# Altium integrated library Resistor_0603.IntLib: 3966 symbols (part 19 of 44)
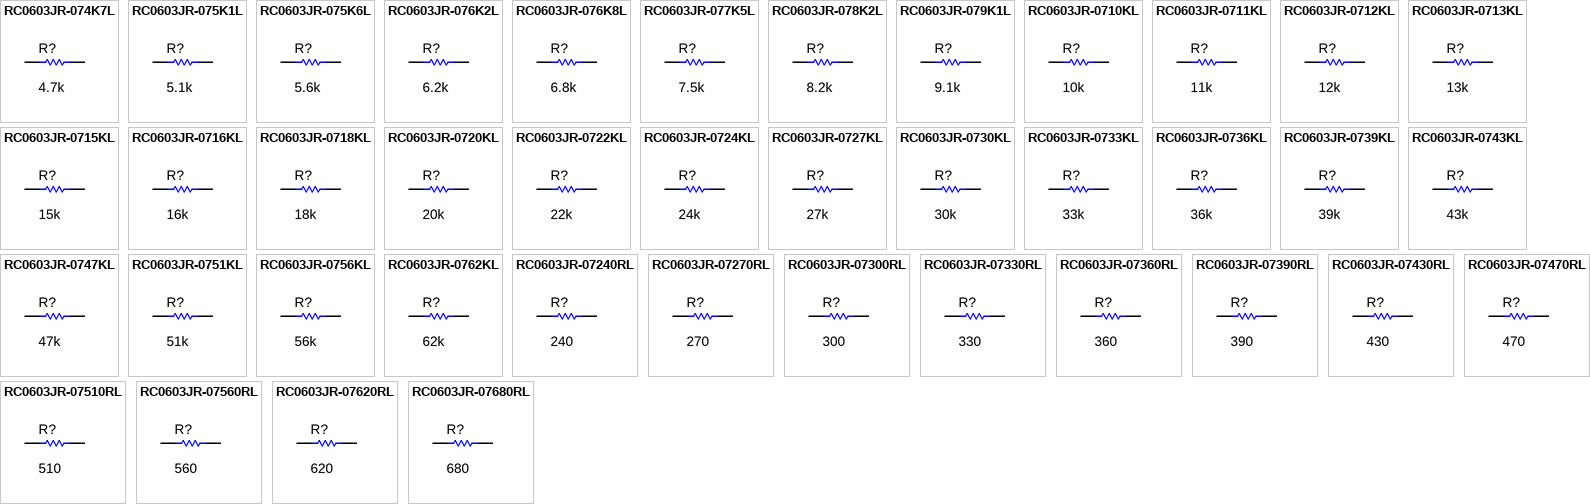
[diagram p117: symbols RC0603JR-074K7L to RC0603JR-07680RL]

## RC0603JR-0736KL
designator R?  ValueDisplayed: 36k  (hidden comment: RC0603JR-0736KL)
RES, 36 k, 5%, 0.1 W, 0603; Manufacturer: Yageo America; CompType: Resistor; Value: 36k; Res_ohm: 36000; Value_Code: 36k0; Tolerance_%: 5; Power_W: 0.1; Value2: 0.1W; VDC_V: 50; TempCo: 100 ppm/C; SizeArea_mm2: 1.28; SizeX_mm: 1.6; SizeY_mm: 0.8; SizeZ_mm: 1; EIA_Code: E24; U/M: EA; AEC Category: Q200
signal-integrity model Resistor
simulation model Resistor
footprint 0603
footprint 0603M
footprint 0603L
footprint 0603_HV
footprint 0603S
pins: 1, 2

## RC0603JR-0739KL
designator R?  ValueDisplayed: 39k  (hidden comment: RC0603JR-0739KL)
RES, 39 k, 5%, 0.1 W, 0603; Manufacturer: Yageo America; CompType: Resistor; Value: 39k; Res_ohm: 39000; Value_Code: 39k0; Tolerance_%: 5; Power_W: 0.1; Value2: 0.1W; VDC_V: 50; TempCo: 100 ppm/C; SizeArea_mm2: 1.28; SizeX_mm: 1.6; SizeY_mm: 0.8; SizeZ_mm: 1; EIA_Code: E24; U/M: EA; AEC Category: Q200
signal-integrity model Resistor
simulation model Resistor
footprint 0603
footprint 0603M
footprint 0603L
footprint 0603_HV
footprint 0603S
pins: 1, 2

## RC0603JR-0743KL
designator R?  ValueDisplayed: 43k  (hidden comment: RC0603JR-0743KL)
RES, 43 k, 5%, 0.1 W, 0603; Manufacturer: Yageo America; CompType: Resistor; Value: 43k; Res_ohm: 43000; Value_Code: 43k0; Tolerance_%: 5; Power_W: 0.1; Value2: 0.1W; VDC_V: 50; TempCo: 100 ppm/C; SizeArea_mm2: 1.28; SizeX_mm: 1.6; SizeY_mm: 0.8; SizeZ_mm: 1; EIA_Code: E24; U/M: EA; AEC Category: Q200
signal-integrity model Resistor
simulation model Resistor
footprint 0603
footprint 0603M
footprint 0603L
footprint 0603_HV
footprint 0603S
pins: 1, 2

## RC0603JR-0747KL
designator R?  ValueDisplayed: 47k  (hidden comment: RC0603JR-0747KL)
RES, 47 k, 5%, 0.1 W, 0603; Manufacturer: Yageo America; CompType: Resistor; Value: 47k; Res_ohm: 47000; Value_Code: 47k0; Tolerance_%: 5; Power_W: 0.1; Value2: 0.1W; VDC_V: 50; TempCo: 100 ppm/C; SizeArea_mm2: 1.28; SizeX_mm: 1.6; SizeY_mm: 0.8; SizeZ_mm: 1; EIA_Code: E24; U/M: EA; AEC Category: Q200; Green_Lifecycle: Active; Green_REACh: Passed
signal-integrity model Resistor
simulation model Resistor
footprint 0603
footprint 0603M
footprint 0603L
footprint 0603_HV
footprint 0603S
pins: 1, 2

## RC0603JR-0751KL
designator R?  ValueDisplayed: 51k  (hidden comment: RC0603JR-0751KL)
RES, 51 k, 5%, 0.1 W, 0603; Manufacturer: Yageo America; CompType: Resistor; Value: 51k; Res_ohm: 51000; Value_Code: 51k0; Tolerance_%: 5; Power_W: 0.1; Value2: 0.1W; VDC_V: 50; TempCo: 100 ppm/C; SizeArea_mm2: 1.28; SizeX_mm: 1.6; SizeY_mm: 0.8; SizeZ_mm: 1; EIA_Code: E24; U/M: EA; AEC Category: Q200; Green_Lifecycle: Active; Green_REACh: Passed
signal-integrity model Resistor
simulation model Resistor
footprint 0603
footprint 0603M
footprint 0603L
footprint 0603_HV
footprint 0603S
pins: 1, 2

## RC0603JR-0756KL
designator R?  ValueDisplayed: 56k  (hidden comment: RC0603JR-0756KL)
RES, 56 k, 5%, 0.1 W, 0603; Manufacturer: Yageo America; CompType: Resistor; Value: 56k; Res_ohm: 56000; Value_Code: 56k0; Tolerance_%: 5; Power_W: 0.1; Value2: 0.1W; VDC_V: 50; TempCo: 100 ppm/C; SizeArea_mm2: 1.28; SizeX_mm: 1.6; SizeY_mm: 0.8; SizeZ_mm: 1; EIA_Code: E24; U/M: EA; AEC Category: Q200
signal-integrity model Resistor
simulation model Resistor
footprint 0603
footprint 0603M
footprint 0603L
footprint 0603_HV
footprint 0603S
pins: 1, 2

## RC0603JR-0762KL
designator R?  ValueDisplayed: 62k  (hidden comment: RC0603JR-0762KL)
RES, 62 k, 5%, 0.1 W, 0603; Manufacturer: Yageo America; CompType: Resistor; Value: 62k; Res_ohm: 62000; Value_Code: 62k0; Tolerance_%: 5; Power_W: 0.1; Value2: 0.1W; VDC_V: 50; TempCo: 100 ppm/C; SizeArea_mm2: 1.28; SizeX_mm: 1.6; SizeY_mm: 0.8; SizeZ_mm: 1; EIA_Code: E24; U/M: EA; AEC Category: Q200
signal-integrity model Resistor
simulation model Resistor
footprint 0603
footprint 0603M
footprint 0603L
footprint 0603_HV
footprint 0603S
pins: 1, 2

## RC0603JR-07240RL
designator R?  ValueDisplayed: 240  (hidden comment: RC0603JR-07240RL)
RES, 240, 5%, 0.1 W, 0603; Manufacturer: Yageo America; CompType: Resistor; Value: 240; Value_Code: 240R; Tolerance_%: 5; Power_W: 0.1; Value2: 0.1W; VDC_V: 50; TempCo: 100 ppm/C; SizeArea_mm2: 1.28; SizeX_mm: 1.6; SizeY_mm: 0.8; SizeZ_mm: 1; EIA_Code: E24; U/M: EA; AEC Category: Q200
signal-integrity model Resistor
simulation model Resistor
footprint 0603
footprint 0603M
footprint 0603L
footprint 0603_HV
footprint 0603S
pins: 1, 2

## RC0603JR-07270RL
designator R?  ValueDisplayed: 270  (hidden comment: RC0603JR-07270RL)
RES, 270, 5%, 0.1 W, 0603; Manufacturer: Yageo America; CompType: Resistor; Value: 270; Value_Code: 270R; Tolerance_%: 5; Power_W: 0.1; Value2: 0.1W; VDC_V: 50; TempCo: 100 ppm/C; SizeArea_mm2: 1.28; SizeX_mm: 1.6; SizeY_mm: 0.8; SizeZ_mm: 1; EIA_Code: E24; U/M: EA; AEC Category: Q200
signal-integrity model Resistor
simulation model Resistor
footprint 0603
footprint 0603M
footprint 0603L
footprint 0603_HV
footprint 0603S
pins: 1, 2

## RC0603JR-07300RL
designator R?  ValueDisplayed: 300  (hidden comment: RC0603JR-07300RL)
RES, 300, 5%, 0.1 W, 0603; Manufacturer: Yageo America; CompType: Resistor; Value: 300; Value_Code: 300R; Tolerance_%: 5; Power_W: 0.1; Value2: 0.1W; VDC_V: 50; TempCo: 100 ppm/C; SizeArea_mm2: 1.28; SizeX_mm: 1.6; SizeY_mm: 0.8; SizeZ_mm: 1; EIA_Code: E24; U/M: EA; AEC Category: Q200; Green_Lifecycle: Active; Green_REACh: Passed
signal-integrity model Resistor
simulation model Resistor
footprint 0603
footprint 0603M
footprint 0603L
footprint 0603_HV
footprint 0603S
pins: 1, 2

## RC0603JR-07330RL
designator R?  ValueDisplayed: 330  (hidden comment: RC0603JR-07330RL)
RES, 330, 5%, 0.1 W, 0603; Manufacturer: Yageo America; CompType: Resistor; Value: 330; Value_Code: 330R; Tolerance_%: 5; Power_W: 0.1; Value2: 0.1W; VDC_V: 50; TempCo: 100 ppm/C; SizeArea_mm2: 1.28; SizeX_mm: 1.6; SizeY_mm: 0.8; SizeZ_mm: 1; EIA_Code: E24; U/M: EA; AEC Category: Q200; Green_Lifecycle: Active; Green_REACh: Passed
signal-integrity model Resistor
simulation model Resistor
footprint 0603
footprint 0603M
footprint 0603L
footprint 0603_HV
footprint 0603S
pins: 1, 2

## RC0603JR-07360RL
designator R?  ValueDisplayed: 360  (hidden comment: RC0603JR-07360RL)
RES, 360, 5%, 0.1 W, 0603; Manufacturer: Yageo America; CompType: Resistor; Value: 360; Value_Code: 360R; Tolerance_%: 5; Power_W: 0.1; Value2: 0.1W; VDC_V: 50; TempCo: 100 ppm/C; SizeArea_mm2: 1.28; SizeX_mm: 1.6; SizeY_mm: 0.8; SizeZ_mm: 1; EIA_Code: E24; U/M: EA; AEC Category: Q200
signal-integrity model Resistor
simulation model Resistor
footprint 0603
footprint 0603M
footprint 0603L
footprint 0603_HV
footprint 0603S
pins: 1, 2

## RC0603JR-07390RL
designator R?  ValueDisplayed: 390  (hidden comment: RC0603JR-07390RL)
RES, 390, 5%, 0.1 W, 0603; Manufacturer: Yageo America; CompType: Resistor; Value: 390; Value_Code: 390R; Tolerance_%: 5; Power_W: 0.1; Value2: 0.1W; VDC_V: 50; TempCo: 100 ppm/C; SizeArea_mm2: 1.28; SizeX_mm: 1.6; SizeY_mm: 0.8; SizeZ_mm: 1; EIA_Code: E24; U/M: EA; AEC Category: Q200
signal-integrity model Resistor
simulation model Resistor
footprint 0603
footprint 0603M
footprint 0603L
footprint 0603_HV
footprint 0603S
pins: 1, 2

## RC0603JR-07430RL
designator R?  ValueDisplayed: 430  (hidden comment: RC0603JR-07430RL)
RES, 430, 5%, 0.1 W, 0603; Manufacturer: Yageo America; CompType: Resistor; Value: 430; Value_Code: 430R; Tolerance_%: 5; Power_W: 0.1; Value2: 0.1W; VDC_V: 50; TempCo: 100 ppm/C; SizeArea_mm2: 1.28; SizeX_mm: 1.6; SizeY_mm: 0.8; SizeZ_mm: 1; EIA_Code: E24; U/M: EA; AEC Category: Q200
signal-integrity model Resistor
simulation model Resistor
footprint 0603
footprint 0603M
footprint 0603L
footprint 0603_HV
footprint 0603S
pins: 1, 2

## RC0603JR-07470RL
designator R?  ValueDisplayed: 470  (hidden comment: RC0603JR-07470RL)
RES, 470, 5%, 0.1 W, 0603; Manufacturer: Yageo America; CompType: Resistor; Value: 470; Value_Code: 470R; Tolerance_%: 5; Power_W: 0.1; Value2: 0.1W; VDC_V: 50; TempCo: 100 ppm/C; SizeArea_mm2: 1.28; SizeX_mm: 1.6; SizeY_mm: 0.8; SizeZ_mm: 1; EIA_Code: E24; U/M: EA; AEC Category: Q200
signal-integrity model Resistor
simulation model Resistor
footprint 0603
footprint 0603M
footprint 0603L
footprint 0603_HV
footprint 0603S
pins: 1, 2

## RC0603JR-07510RL
designator R?  ValueDisplayed: 510  (hidden comment: RC0603JR-07510RL)
RES, 510, 5%, 0.1 W, 0603; Manufacturer: Yageo America; CompType: Resistor; Value: 510; Value_Code: 510R; Tolerance_%: 5; Power_W: 0.1; Value2: 0.1W; VDC_V: 50; TempCo: 100 ppm/C; SizeArea_mm2: 1.28; SizeX_mm: 1.6; SizeY_mm: 0.8; SizeZ_mm: 1; EIA_Code: E24; U/M: EA; AEC Category: Q200; Green_Lifecycle: Active; Green_REACh: Passed
signal-integrity model Resistor
simulation model Resistor
footprint 0603
footprint 0603M
footprint 0603L
footprint 0603_HV
footprint 0603S
pins: 1, 2

## RC0603JR-07560RL
designator R?  ValueDisplayed: 560  (hidden comment: RC0603JR-07560RL)
RES, 560, 5%, 0.1 W, 0603; Manufacturer: Yageo America; CompType: Resistor; Value: 560; Value_Code: 560R; Tolerance_%: 5; Power_W: 0.1; Value2: 0.1W; VDC_V: 50; TempCo: 100 ppm/C; SizeArea_mm2: 1.28; SizeX_mm: 1.6; SizeY_mm: 0.8; SizeZ_mm: 1; EIA_Code: E24; U/M: EA; AEC Category: Q200
signal-integrity model Resistor
simulation model Resistor
footprint 0603
footprint 0603M
footprint 0603L
footprint 0603_HV
footprint 0603S
pins: 1, 2

## RC0603JR-07620RL
designator R?  ValueDisplayed: 620  (hidden comment: RC0603JR-07620RL)
RES, 620, 5%, 0.1 W, 0603; Manufacturer: Yageo America; CompType: Resistor; Value: 620; Value_Code: 620R; Tolerance_%: 5; Power_W: 0.1; Value2: 0.1W; VDC_V: 50; TempCo: 100 ppm/C; SizeArea_mm2: 1.28; SizeX_mm: 1.6; SizeY_mm: 0.8; SizeZ_mm: 1; EIA_Code: E24; U/M: EA; AEC Category: Q200
signal-integrity model Resistor
simulation model Resistor
footprint 0603
footprint 0603M
footprint 0603L
footprint 0603_HV
footprint 0603S
pins: 1, 2

## RC0603JR-07680RL
designator R?  ValueDisplayed: 680  (hidden comment: RC0603JR-07680RL)
RES, 680, 5%, 0.1 W, 0603; Manufacturer: Yageo America; CompType: Resistor; Value: 680; Value_Code: 680R; Tolerance_%: 5; Power_W: 0.1; Value2: 0.1W; VDC_V: 50; TempCo: 100 ppm/C; SizeArea_mm2: 1.28; SizeX_mm: 1.6; SizeY_mm: 0.8; SizeZ_mm: 1; EIA_Code: E24; U/M: EA; AEC Category: Q200
signal-integrity model Resistor
simulation model Resistor
footprint 0603
footprint 0603M
footprint 0603L
footprint 0603_HV
footprint 0603S
pins: 1, 2

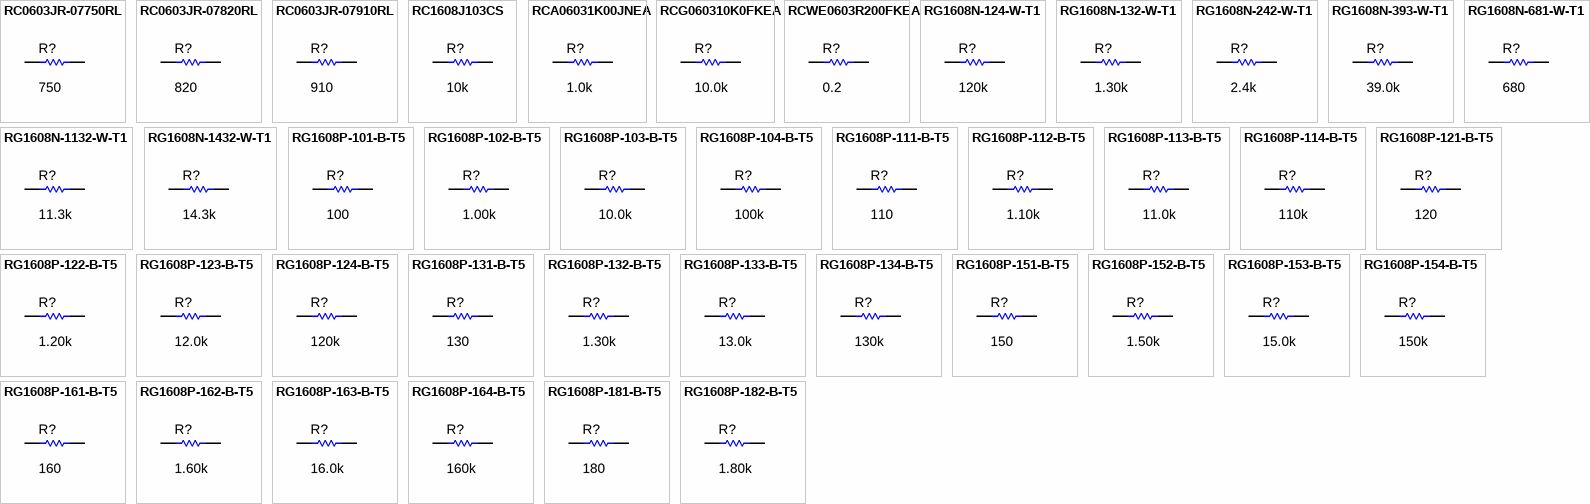
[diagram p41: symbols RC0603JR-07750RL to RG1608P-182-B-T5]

## RC0603JR-07750RL
designator R?  ValueDisplayed: 750  (hidden comment: RC0603JR-07750RL)
RES, 750, 5%, 0.1 W, 0603; Manufacturer: Yageo America; CompType: Resistor; Value: 750; Value_Code: 750R; Tolerance_%: 5; Power_W: 0.1; Value2: 0.1W; VDC_V: 50; TempCo: 100 ppm/C; SizeArea_mm2: 1.28; SizeX_mm: 1.6; SizeY_mm: 0.8; SizeZ_mm: 1; EIA_Code: E24; U/M: EA; AEC Category: Q200; Green_Lifecycle: Active; Green_REACh: Passed
signal-integrity model Resistor
simulation model Resistor
footprint 0603
footprint 0603M
footprint 0603L
footprint 0603_HV
footprint 0603S
pins: 1, 2

## RC0603JR-07820RL
designator R?  ValueDisplayed: 820  (hidden comment: RC0603JR-07820RL)
RES, 820, 5%, 0.1 W, 0603; Manufacturer: Yageo America; CompType: Resistor; Value: 820; Value_Code: 820R; Tolerance_%: 5; Power_W: 0.1; Value2: 0.1W; VDC_V: 50; TempCo: 100 ppm/C; SizeArea_mm2: 1.28; SizeX_mm: 1.6; SizeY_mm: 0.8; SizeZ_mm: 1; EIA_Code: E24; U/M: EA; AEC Category: Q200; Green_Lifecycle: Active; Green_REACh: Passed
signal-integrity model Resistor
simulation model Resistor
footprint 0603
footprint 0603M
footprint 0603L
footprint 0603_HV
footprint 0603S
pins: 1, 2

## RC0603JR-07910RL
designator R?  ValueDisplayed: 910  (hidden comment: RC0603JR-07910RL)
RES, 910, 5%, 0.1 W, 0603; Manufacturer: Yageo America; CompType: Resistor; Value: 910; Value_Code: 910R; Tolerance_%: 5; Power_W: 0.1; Value2: 0.1W; VDC_V: 50; TempCo: 100 ppm/C; SizeArea_mm2: 1.28; SizeX_mm: 1.6; SizeY_mm: 0.8; SizeZ_mm: 1; EIA_Code: E24; U/M: EA; AEC Category: Q200
signal-integrity model Resistor
simulation model Resistor
footprint 0603
footprint 0603M
footprint 0603L
footprint 0603_HV
footprint 0603S
pins: 1, 2

## RC1608J103CS
designator R?  ValueDisplayed: 10k  (hidden comment: RC1608J103CS)
RES, 10 k, 5%, 0.1 W, 0603; Manufacturer: Samsung Electro-Mechanics; CompType: Resistor; Value: 10k; Res_ohm: 10000; Value_Code: 10k0; Tolerance_%: 5; Power_W: 0.1; Value2: 0.1W; VDC_V: 31; TempCo: 100 ppm/C; SizeArea_mm2: 1.28; SizeX_mm: 1.6; SizeY_mm: 0.8; SizeZ_mm: 1; EIA_Code: E24; U/M: EA; AEC Category: Q200; AEC Qualified: N; Green_Lifecycle: Active; Green_REACh: Passed
signal-integrity model Resistor
simulation model Resistor
footprint 0603
footprint 0603M
footprint 0603L
footprint 0603_HV
footprint 0603S
pins: 1, 2

## RCA06031K00JNEA
designator R?  ValueDisplayed: 1.0k  (hidden comment: RCA06031K00JNEA)
RES, 1.0 k, 5%, 0.1 W, AEC-Q200 Grade 0, 0603; Manufacturer: Vishay-Dale; CompType: Resistor; Value: 1.0k; Res_ohm: 1000; Value_Code: 1k00; Tolerance_%: 5; Power_W: 0.1; Value2: 0.1W; VDC_V: 75; TempCo: 200 ppm/C; SizeArea_mm2: 1.28; SizeX_mm: 1.6; SizeY_mm: 0.8; SizeZ_mm: 1; EIA_Code: E24; U/M: EA; AEC Category: Q200; AEC Qualified: Y; AEC Grade: 0
signal-integrity model Resistor
simulation model Resistor
footprint 0603
footprint 0603M
footprint 0603L
footprint 0603_HV
footprint 0603S
pins: 1, 2

## RCG060310K0FKEA
designator R?  ValueDisplayed: 10.0k  (hidden comment: RCG060310K0FKEA)
RES, 10.0 k, 1%, 0.1 W, 0603; Manufacturer: Vishay Draloric; CompType: Resistor; Value: 10.0k; Res_ohm: 10000; Value_Code: 10k0; Tolerance_%: 1; Power_W: 0.1; Value2: 0.1W; VDC_V: 75; TempCo: 100 ppm/C; SizeArea_mm2: 1.28; SizeX_mm: 1.6; SizeY_mm: 0.8; EIA_Code: E96; U/M: EA; AEC Category: Q200; AEC Qualified: N
signal-integrity model Resistor
simulation model Resistor
footprint 0603
footprint 0603M
footprint 0603L
footprint 0603_HV
footprint 0603S
pins: 1, 2

## RCWE0603R200FKEA
designator R?  ValueDisplayed: 0.2  (hidden comment: RCWE0603R200FKEA)
RES, 0.2, 1%, 0.2 W, AEC-Q200 Grade 0, 0603; Manufacturer: Vishay-Dale; CompType: Resistor; Value: 0.2; Value_Code: R200; Tolerance_%: 1; Value2: 0.2W; TempCo: 100 ppm/C; SizeArea_mm2: 1.28; SizeX_mm: 1.6; SizeY_mm: 0.8; EIA_Code: E96; U/M: EA; AEC Category: Q200; AEC Qualified: Y; AEC Grade: 0
signal-integrity model Resistor
simulation model Resistor
footprint 0603
footprint 0603M
footprint 0603L
footprint 0603_HV
footprint 0603S
pins: 1, 2

## RG1608N-124-W-T1
designator R?  ValueDisplayed: 120k  (hidden comment: RG1608N-124-W-T1)
RES, 120 k, 0.05%, 0.1 W, AEC-Q200 Grade 0, 0603; Manufacturer: Susumu Co Ltd; CompType: Resistor; Value: 120k; Res_ohm: 120000; Tolerance_%: 0.05; Power_W: 0.1; Value2: 0.1W; VDC_V: 75; TempCo: 10 ppm/C; SizeArea_mm2: 1.28; SizeX_mm: 1.6; SizeY_mm: 0.8; SizeZ_mm: 1; U/M: EA; AEC Category: Q200; AEC Qualified: Y; AEC Grade: 0
signal-integrity model Resistor
simulation model Resistor
footprint 0603
footprint 0603M
footprint 0603L
footprint 0603_HV
footprint 0603S
pins: 1, 2

## RG1608N-132-W-T1
designator R?  ValueDisplayed: 1.30k  (hidden comment: RG1608N-132-W-T1)
RES, 1.30 k, 0.05%, 0.1 W, AEC-Q200 Grade 0, 0603; Manufacturer: Susumu Co Ltd; CompType: Resistor; Value: 1.30k; Res_ohm: 1300; Value_Code: 1k30; Tolerance_%: 0.05; Power_W: 0.1; Value2: 0.1W; VDC_V: 75; TempCo: 10 ppm/C; SizeArea_mm2: 1.28; SizeX_mm: 1.6; SizeY_mm: 0.8; SizeZ_mm: 1; U/M: EA; AEC Category: Q200; AEC Qualified: Y; AEC Grade: 0
signal-integrity model Resistor
simulation model Resistor
footprint 0603
footprint 0603M
footprint 0603L
footprint 0603_HV
footprint 0603S
pins: 1, 2

## RG1608N-242-W-T1
designator R?  ValueDisplayed: 2.4k  (hidden comment: RG1608N-242-W-T1)
RES, 2.4 k, 0.05%, 0.1 W, AEC-Q200 Grade 0, 0603; Manufacturer: Susumu Co Ltd; CompType: Resistor; Value: 2.4k; Res_ohm: 2400; Value_Code: 2k40; Tolerance_%: 0.05; Power_W: 0.1; Value2: 0.1W; VDC_V: 75; TempCo: 10 ppm/C; SizeArea_mm2: 1.28; SizeX_mm: 1.6; SizeY_mm: 0.8; SizeZ_mm: 1; U/M: EA; AEC Category: Q200; AEC Qualified: Y; AEC Grade: 0
signal-integrity model Resistor
simulation model Resistor
footprint 0603
footprint 0603M
footprint 0603L
footprint 0603_HV
footprint 0603S
pins: 1, 2

## RG1608N-393-W-T1
designator R?  ValueDisplayed: 39.0k  (hidden comment: RG1608N-393-W-T1)
RES, 39.0 k, 0.05%, 0.1 W, AEC-Q200 Grade 0, 0603; Manufacturer: Susumu Co Ltd; CompType: Resistor; Value: 39.0k; Res_ohm: 39000; Value_Code: 39k0; Tolerance_%: 0.05; Power_W: 0.1; Value2: 0.1W; VDC_V: 75; TempCo: 10 ppm/C; SizeArea_mm2: 1.28; SizeX_mm: 1.6; SizeY_mm: 0.8; SizeZ_mm: 1; U/M: EA; AEC Category: Q200; AEC Qualified: Y; AEC Grade: 0
signal-integrity model Resistor
simulation model Resistor
footprint 0603
footprint 0603M
footprint 0603L
footprint 0603_HV
footprint 0603S
pins: 1, 2

## RG1608N-681-W-T1
designator R?  ValueDisplayed: 680  (hidden comment: RG1608N-681-W-T1)
RES, 680, 0.05%, 0.1 W, AEC-Q200 Grade 0, 0603; Manufacturer: Susumu Co Ltd; CompType: Resistor; Value: 680; Value_Code: 680R; Tolerance_%: 0.05; Power_W: 0.1; Value2: 0.1W; VDC_V: 75; TempCo: 10 ppm/C; SizeArea_mm2: 1.28; SizeX_mm: 1.6; SizeY_mm: 0.8; SizeZ_mm: 1; U/M: EA; AEC Category: Q200; AEC Qualified: Y; AEC Grade: 0
signal-integrity model Resistor
simulation model Resistor
footprint 0603
footprint 0603M
footprint 0603L
footprint 0603_HV
footprint 0603S
pins: 1, 2

## RG1608N-1132-W-T1
designator R?  ValueDisplayed: 11.3k  (hidden comment: RG1608N-1132-W-T1)
RES, 11.3 k, 0.05%, 0.1 W, AEC-Q200 Grade 0, 0603; Manufacturer: Susumu Co Ltd; CompType: Resistor; Value: 11.3k; Res_ohm: 11300; Value_Code: 11k3; Tolerance_%: 0.05; Power_W: 0.1; Value2: 0.1W; VDC_V: 75; TempCo: 10 ppm/C; SizeArea_mm2: 1.28; SizeX_mm: 1.6; SizeY_mm: 0.8; SizeZ_mm: 1; U/M: EA; AEC Category: Q200; AEC Qualified: Y; AEC Grade: 0
signal-integrity model Resistor
simulation model Resistor
footprint 0603
footprint 0603M
footprint 0603L
footprint 0603_HV
footprint 0603S
pins: 1, 2

## RG1608N-1432-W-T1
designator R?  ValueDisplayed: 14.3k  (hidden comment: RG1608N-1432-W-T1)
RES, 14.3 k, 0.05%, 0.1 W, AEC-Q200 Grade 0, 0603; Manufacturer: Susumu Co Ltd; CompType: Resistor; Value: 14.3k; Res_ohm: 14300; Value_Code: 14k3; Tolerance_%: 0.05; Power_W: 0.1; Value2: 0.1W; VDC_V: 75; TempCo: 10 ppm/C; SizeArea_mm2: 1.28; SizeX_mm: 1.6; SizeY_mm: 0.8; SizeZ_mm: 1; U/M: EA; AEC Category: Q200; AEC Qualified: Y; AEC Grade: 0
signal-integrity model Resistor
simulation model Resistor
footprint 0603
footprint 0603M
footprint 0603L
footprint 0603_HV
footprint 0603S
pins: 1, 2

## RG1608P-101-B-T5
designator R?  ValueDisplayed: 100  (hidden comment: RG1608P-101-B-T5)
RES, 100, 0.1%, 0.1 W, 0603; Manufacturer: Susumu Co Ltd; CompType: Resistor; Value: 100; Value_Code: 100R; Tolerance_%: 0.1; Value2: 0.1W; VDC_V: 75; TempCo: 25 ppm/C; SizeArea_mm2: 1.28; SizeX_mm: 1.6; SizeY_mm: 0.8; SizeZ_mm: 1; EIA_Code: E192; U/M: EA; AEC Category: Q200; Green_Lifecycle: Active; Green_REACh: Passed
signal-integrity model Resistor
simulation model Resistor
footprint 0603
footprint 0603M
footprint 0603L
footprint 0603_HV
footprint 0603S
pins: 1, 2

## RG1608P-102-B-T5
designator R?  ValueDisplayed: 1.00k  (hidden comment: RG1608P-102-B-T5)
RES, 1.00 k, 0.1%, 0.1 W, 0603; Manufacturer: Susumu Co Ltd; CompType: Resistor; Value: 1.00k; Res_ohm: 1000; Value_Code: 1k00; Tolerance_%: 0.1; Value2: 0.1W; VDC_V: 75; TempCo: 25 ppm/C; SizeArea_mm2: 1.28; SizeX_mm: 1.6; SizeY_mm: 0.8; SizeZ_mm: 1; EIA_Code: E192; U/M: EA; AEC Category: Q200; Green_Lifecycle: Active; Green_REACh: Passed
signal-integrity model Resistor
simulation model Resistor
footprint 0603
footprint 0603M
footprint 0603L
footprint 0603_HV
footprint 0603S
pins: 1, 2

## RG1608P-103-B-T5
designator R?  ValueDisplayed: 10.0k  (hidden comment: RG1608P-103-B-T5)
RES, 10.0 k, 0.1%, 0.1 W, 0603; Manufacturer: Susumu Co Ltd; CompType: Resistor; Value: 10.0k; Res_ohm: 10000; Value_Code: 10k0; Tolerance_%: 0.1; Value2: 0.1W; VDC_V: 75; TempCo: 25 ppm/C; SizeArea_mm2: 1.28; SizeX_mm: 1.6; SizeY_mm: 0.8; SizeZ_mm: 1; EIA_Code: E192; U/M: EA; AEC Category: Q200; Green_Lifecycle: Active; Green_REACh: Passed
signal-integrity model Resistor
simulation model Resistor
footprint 0603
footprint 0603M
footprint 0603L
footprint 0603_HV
footprint 0603S
pins: 1, 2

## RG1608P-104-B-T5
designator R?  ValueDisplayed: 100k  (hidden comment: RG1608P-104-B-T5)
RES, 100 k, 0.1%, 0.1 W, 0603; Manufacturer: Susumu Co Ltd; CompType: Resistor; Value: 100k; Res_ohm: 100000; Tolerance_%: 0.1; Value2: 0.1W; VDC_V: 75; TempCo: 25 ppm/C; SizeArea_mm2: 1.28; SizeX_mm: 1.6; SizeY_mm: 0.8; SizeZ_mm: 1; EIA_Code: E192; U/M: EA; AEC Category: Q200; Green_Lifecycle: Active; Green_REACh: Passed
signal-integrity model Resistor
simulation model Resistor
footprint 0603
footprint 0603M
footprint 0603L
footprint 0603_HV
footprint 0603S
pins: 1, 2

## RG1608P-111-B-T5
designator R?  ValueDisplayed: 110  (hidden comment: RG1608P-111-B-T5)
RES, 110, 0.1%, 0.1 W, 0603; Manufacturer: Susumu Co Ltd; CompType: Resistor; Value: 110; Value_Code: 110R; Tolerance_%: 0.1; Value2: 0.1W; VDC_V: 75; TempCo: 25 ppm/C; SizeArea_mm2: 1.28; SizeX_mm: 1.6; SizeY_mm: 0.8; SizeZ_mm: 1; EIA_Code: E192; U/M: EA; AEC Category: Q200
signal-integrity model Resistor
simulation model Resistor
footprint 0603
footprint 0603M
footprint 0603L
footprint 0603_HV
footprint 0603S
pins: 1, 2

## RG1608P-112-B-T5
designator R?  ValueDisplayed: 1.10k  (hidden comment: RG1608P-112-B-T5)
RES, 1.10 k, 0.1%, 0.1 W, 0603; Manufacturer: Susumu Co Ltd; CompType: Resistor; Value: 1.10k; Res_ohm: 1100; Value_Code: 1k10; Tolerance_%: 0.1; Value2: 0.1W; VDC_V: 75; TempCo: 25 ppm/C; SizeArea_mm2: 1.28; SizeX_mm: 1.6; SizeY_mm: 0.8; SizeZ_mm: 1; EIA_Code: E192; U/M: EA; AEC Category: Q200
signal-integrity model Resistor
simulation model Resistor
footprint 0603
footprint 0603M
footprint 0603L
footprint 0603_HV
footprint 0603S
pins: 1, 2

## RG1608P-113-B-T5
designator R?  ValueDisplayed: 11.0k  (hidden comment: RG1608P-113-B-T5)
RES, 11.0 k, 0.1%, 0.1 W, 0603; Manufacturer: Susumu Co Ltd; CompType: Resistor; Value: 11.0k; Res_ohm: 11000; Value_Code: 11k0; Tolerance_%: 0.1; Value2: 0.1W; VDC_V: 75; TempCo: 25 ppm/C; SizeArea_mm2: 1.28; SizeX_mm: 1.6; SizeY_mm: 0.8; SizeZ_mm: 1; EIA_Code: E192; U/M: EA; AEC Category: Q200
signal-integrity model Resistor
simulation model Resistor
footprint 0603
footprint 0603M
footprint 0603L
footprint 0603_HV
footprint 0603S
pins: 1, 2

## RG1608P-114-B-T5
designator R?  ValueDisplayed: 110k  (hidden comment: RG1608P-114-B-T5)
RES, 110 k, 0.1%, 0.1 W, 0603; Manufacturer: Susumu Co Ltd; CompType: Resistor; Value: 110k; Res_ohm: 110000; Tolerance_%: 0.1; Value2: 0.1W; VDC_V: 75; TempCo: 25 ppm/C; SizeArea_mm2: 1.28; SizeX_mm: 1.6; SizeY_mm: 0.8; SizeZ_mm: 1; EIA_Code: E192; U/M: EA; AEC Category: Q200
signal-integrity model Resistor
simulation model Resistor
footprint 0603
footprint 0603M
footprint 0603L
footprint 0603_HV
footprint 0603S
pins: 1, 2

## RG1608P-121-B-T5
designator R?  ValueDisplayed: 120  (hidden comment: RG1608P-121-B-T5)
RES, 120, 0.1%, 0.1 W, 0603; Manufacturer: Susumu Co Ltd; CompType: Resistor; Value: 120; Value_Code: 120R; Tolerance_%: 0.1; Value2: 0.1W; VDC_V: 75; TempCo: 25 ppm/C; SizeArea_mm2: 1.28; SizeX_mm: 1.6; SizeY_mm: 0.8; SizeZ_mm: 1; EIA_Code: E192; U/M: EA; AEC Category: Q200
signal-integrity model Resistor
simulation model Resistor
footprint 0603
footprint 0603M
footprint 0603L
footprint 0603_HV
footprint 0603S
pins: 1, 2

## RG1608P-122-B-T5
designator R?  ValueDisplayed: 1.20k  (hidden comment: RG1608P-122-B-T5)
RES, 1.20 k, 0.1%, 0.1 W, 0603; Manufacturer: Susumu Co Ltd; CompType: Resistor; Value: 1.20k; Res_ohm: 1200; Value_Code: 1k20; Tolerance_%: 0.1; Value2: 0.1W; VDC_V: 75; TempCo: 25 ppm/C; SizeArea_mm2: 1.28; SizeX_mm: 1.6; SizeY_mm: 0.8; SizeZ_mm: 1; EIA_Code: E192; U/M: EA; AEC Category: Q200
signal-integrity model Resistor
simulation model Resistor
footprint 0603
footprint 0603M
footprint 0603L
footprint 0603_HV
footprint 0603S
pins: 1, 2

## RG1608P-123-B-T5
designator R?  ValueDisplayed: 12.0k  (hidden comment: RG1608P-123-B-T5)
RES, 12.0 k, 0.1%, 0.1 W, 0603; Manufacturer: Susumu Co Ltd; CompType: Resistor; Value: 12.0k; Res_ohm: 12000; Value_Code: 12k0; Tolerance_%: 0.1; Value2: 0.1W; VDC_V: 75; TempCo: 25 ppm/C; SizeArea_mm2: 1.28; SizeX_mm: 1.6; SizeY_mm: 0.8; SizeZ_mm: 1; EIA_Code: E192; U/M: EA; AEC Category: Q200
signal-integrity model Resistor
simulation model Resistor
footprint 0603
footprint 0603M
footprint 0603L
footprint 0603_HV
footprint 0603S
pins: 1, 2

## RG1608P-124-B-T5
designator R?  ValueDisplayed: 120k  (hidden comment: RG1608P-124-B-T5)
RES, 120 k, 0.1%, 0.1 W, 0603; Manufacturer: Susumu Co Ltd; CompType: Resistor; Value: 120k; Res_ohm: 120000; Tolerance_%: 0.1; Value2: 0.1W; VDC_V: 75; TempCo: 25 ppm/C; SizeArea_mm2: 1.28; SizeX_mm: 1.6; SizeY_mm: 0.8; SizeZ_mm: 1; EIA_Code: E192; U/M: EA; AEC Category: Q200
signal-integrity model Resistor
simulation model Resistor
footprint 0603
footprint 0603M
footprint 0603L
footprint 0603_HV
footprint 0603S
pins: 1, 2

## RG1608P-131-B-T5
designator R?  ValueDisplayed: 130  (hidden comment: RG1608P-131-B-T5)
RES, 130, 0.1%, 0.1 W, 0603; Manufacturer: Susumu Co Ltd; CompType: Resistor; Value: 130; Value_Code: 130R; Tolerance_%: 0.1; Value2: 0.1W; VDC_V: 75; TempCo: 25 ppm/C; SizeArea_mm2: 1.28; SizeX_mm: 1.6; SizeY_mm: 0.8; SizeZ_mm: 1; EIA_Code: E192; U/M: EA; AEC Category: Q200
signal-integrity model Resistor
simulation model Resistor
footprint 0603
footprint 0603M
footprint 0603L
footprint 0603_HV
footprint 0603S
pins: 1, 2

## RG1608P-132-B-T5
designator R?  ValueDisplayed: 1.30k  (hidden comment: RG1608P-132-B-T5)
RES, 1.30 k, 0.1%, 0.1 W, 0603; Manufacturer: Susumu Co Ltd; CompType: Resistor; Value: 1.30k; Res_ohm: 1300; Value_Code: 1k30; Tolerance_%: 0.1; Value2: 0.1W; VDC_V: 75; TempCo: 25 ppm/C; SizeArea_mm2: 1.28; SizeX_mm: 1.6; SizeY_mm: 0.8; SizeZ_mm: 1; EIA_Code: E192; U/M: EA; AEC Category: Q200
signal-integrity model Resistor
simulation model Resistor
footprint 0603
footprint 0603M
footprint 0603L
footprint 0603_HV
footprint 0603S
pins: 1, 2

## RG1608P-133-B-T5
designator R?  ValueDisplayed: 13.0k  (hidden comment: RG1608P-133-B-T5)
RES, 13.0 k, 0.1%, 0.1 W, 0603; Manufacturer: Susumu Co Ltd; CompType: Resistor; Value: 13.0k; Res_ohm: 13000; Value_Code: 13k0; Tolerance_%: 0.1; Value2: 0.1W; VDC_V: 75; TempCo: 25 ppm/C; SizeArea_mm2: 1.28; SizeX_mm: 1.6; SizeY_mm: 0.8; SizeZ_mm: 1; EIA_Code: E192; U/M: EA; AEC Category: Q200
signal-integrity model Resistor
simulation model Resistor
footprint 0603
footprint 0603M
footprint 0603L
footprint 0603_HV
footprint 0603S
pins: 1, 2

## RG1608P-134-B-T5
designator R?  ValueDisplayed: 130k  (hidden comment: RG1608P-134-B-T5)
RES, 130 k, 0.1%, 0.1 W, 0603; Manufacturer: Susumu Co Ltd; CompType: Resistor; Value: 130k; Res_ohm: 130000; Tolerance_%: 0.1; Value2: 0.1W; VDC_V: 75; TempCo: 25 ppm/C; SizeArea_mm2: 1.28; SizeX_mm: 1.6; SizeY_mm: 0.8; SizeZ_mm: 1; EIA_Code: E192; U/M: EA; AEC Category: Q200
signal-integrity model Resistor
simulation model Resistor
footprint 0603
footprint 0603M
footprint 0603L
footprint 0603_HV
footprint 0603S
pins: 1, 2

## RG1608P-151-B-T5
designator R?  ValueDisplayed: 150  (hidden comment: RG1608P-151-B-T5)
RES, 150, 0.1%, 0.1 W, 0603; Manufacturer: Susumu Co Ltd; CompType: Resistor; Value: 150; Value_Code: 150R; Tolerance_%: 0.1; Value2: 0.1W; VDC_V: 75; TempCo: 25 ppm/C; SizeArea_mm2: 1.28; SizeX_mm: 1.6; SizeY_mm: 0.8; SizeZ_mm: 1; EIA_Code: E192; U/M: EA; AEC Category: Q200
signal-integrity model Resistor
simulation model Resistor
footprint 0603
footprint 0603M
footprint 0603L
footprint 0603_HV
footprint 0603S
pins: 1, 2

## RG1608P-152-B-T5
designator R?  ValueDisplayed: 1.50k  (hidden comment: RG1608P-152-B-T5)
RES, 1.50 k, 0.1%, 0.1 W, 0603; Manufacturer: Susumu Co Ltd; CompType: Resistor; Value: 1.50k; Res_ohm: 1500; Value_Code: 1k50; Tolerance_%: 0.1; Value2: 0.1W; VDC_V: 75; TempCo: 25 ppm/C; SizeArea_mm2: 1.28; SizeX_mm: 1.6; SizeY_mm: 0.8; SizeZ_mm: 1; EIA_Code: E192; U/M: EA; AEC Category: Q200
signal-integrity model Resistor
simulation model Resistor
footprint 0603
footprint 0603M
footprint 0603L
footprint 0603_HV
footprint 0603S
pins: 1, 2

## RG1608P-153-B-T5
designator R?  ValueDisplayed: 15.0k  (hidden comment: RG1608P-153-B-T5)
RES, 15.0 k, 0.1%, 0.1 W, 0603; Manufacturer: Susumu Co Ltd; CompType: Resistor; Value: 15.0k; Res_ohm: 15000; Value_Code: 15k0; Tolerance_%: 0.1; Value2: 0.1W; VDC_V: 75; TempCo: 25 ppm/C; SizeArea_mm2: 1.28; SizeX_mm: 1.6; SizeY_mm: 0.8; SizeZ_mm: 1; EIA_Code: E192; U/M: EA; AEC Category: Q200; Green_Lifecycle: Active; Green_REACh: Passed
signal-integrity model Resistor
simulation model Resistor
footprint 0603
footprint 0603M
footprint 0603L
footprint 0603_HV
footprint 0603S
pins: 1, 2

## RG1608P-154-B-T5
designator R?  ValueDisplayed: 150k  (hidden comment: RG1608P-154-B-T5)
RES, 150 k, 0.1%, 0.1 W, 0603; Manufacturer: Susumu Co Ltd; CompType: Resistor; Value: 150k; Res_ohm: 150000; Tolerance_%: 0.1; Value2: 0.1W; VDC_V: 75; TempCo: 25 ppm/C; SizeArea_mm2: 1.28; SizeX_mm: 1.6; SizeY_mm: 0.8; SizeZ_mm: 1; EIA_Code: E192; U/M: EA; AEC Category: Q200; Green_Lifecycle: Active; Green_REACh: Passed
signal-integrity model Resistor
simulation model Resistor
footprint 0603
footprint 0603M
footprint 0603L
footprint 0603_HV
footprint 0603S
pins: 1, 2

## RG1608P-161-B-T5
designator R?  ValueDisplayed: 160  (hidden comment: RG1608P-161-B-T5)
RES, 160, 0.1%, 0.1 W, 0603; Manufacturer: Susumu Co Ltd; CompType: Resistor; Value: 160; Value_Code: 160R; Tolerance_%: 0.1; Value2: 0.1W; VDC_V: 75; TempCo: 25 ppm/C; SizeArea_mm2: 1.28; SizeX_mm: 1.6; SizeY_mm: 0.8; SizeZ_mm: 1; EIA_Code: E192; U/M: EA; AEC Category: Q200
signal-integrity model Resistor
simulation model Resistor
footprint 0603
footprint 0603M
footprint 0603L
footprint 0603_HV
footprint 0603S
pins: 1, 2

## RG1608P-162-B-T5
designator R?  ValueDisplayed: 1.60k  (hidden comment: RG1608P-162-B-T5)
RES, 1.60 k, 0.1%, 0.1 W, 0603; Manufacturer: Susumu Co Ltd; CompType: Resistor; Value: 1.60k; Res_ohm: 1600; Value_Code: 1k60; Tolerance_%: 0.1; Value2: 0.1W; VDC_V: 75; TempCo: 25 ppm/C; SizeArea_mm2: 1.28; SizeX_mm: 1.6; SizeY_mm: 0.8; SizeZ_mm: 1; EIA_Code: E192; U/M: EA; AEC Category: Q200
signal-integrity model Resistor
simulation model Resistor
footprint 0603
footprint 0603M
footprint 0603L
footprint 0603_HV
footprint 0603S
pins: 1, 2

## RG1608P-163-B-T5
designator R?  ValueDisplayed: 16.0k  (hidden comment: RG1608P-163-B-T5)
RES, 16.0 k, 0.1%, 0.1 W, 0603; Manufacturer: Susumu Co Ltd; CompType: Resistor; Value: 16.0k; Res_ohm: 16000; Value_Code: 16k0; Tolerance_%: 0.1; Value2: 0.1W; VDC_V: 75; TempCo: 25 ppm/C; SizeArea_mm2: 1.28; SizeX_mm: 1.6; SizeY_mm: 0.8; SizeZ_mm: 1; EIA_Code: E192; U/M: EA; AEC Category: Q200; Green_Lifecycle: Active; Green_REACh: Passed
signal-integrity model Resistor
simulation model Resistor
footprint 0603
footprint 0603M
footprint 0603L
footprint 0603_HV
footprint 0603S
pins: 1, 2

## RG1608P-164-B-T5
designator R?  ValueDisplayed: 160k  (hidden comment: RG1608P-164-B-T5)
RES, 160 k, 0.1%, 0.1 W, 0603; Manufacturer: Susumu Co Ltd; CompType: Resistor; Value: 160k; Res_ohm: 160000; Tolerance_%: 0.1; Value2: 0.1W; VDC_V: 75; TempCo: 25 ppm/C; SizeArea_mm2: 1.28; SizeX_mm: 1.6; SizeY_mm: 0.8; SizeZ_mm: 1; EIA_Code: E192; U/M: EA; AEC Category: Q200; Green_Lifecycle: Active; Green_REACh: Passed
signal-integrity model Resistor
simulation model Resistor
footprint 0603
footprint 0603M
footprint 0603L
footprint 0603_HV
footprint 0603S
pins: 1, 2

## RG1608P-181-B-T5
designator R?  ValueDisplayed: 180  (hidden comment: RG1608P-181-B-T5)
RES, 180, 0.1%, 0.1 W, 0603; Manufacturer: Susumu Co Ltd; CompType: Resistor; Value: 180; Value_Code: 180R; Tolerance_%: 0.1; Value2: 0.1W; VDC_V: 75; TempCo: 25 ppm/C; SizeArea_mm2: 1.28; SizeX_mm: 1.6; SizeY_mm: 0.8; SizeZ_mm: 1; EIA_Code: E192; U/M: EA; AEC Category: Q200
signal-integrity model Resistor
simulation model Resistor
footprint 0603
footprint 0603M
footprint 0603L
footprint 0603_HV
footprint 0603S
pins: 1, 2

## RG1608P-182-B-T5
designator R?  ValueDisplayed: 1.80k  (hidden comment: RG1608P-182-B-T5)
RES, 1.80 k, 0.1%, 0.1 W, 0603; Manufacturer: Susumu Co Ltd; CompType: Resistor; Value: 1.80k; Res_ohm: 1800; Value_Code: 1k80; Tolerance_%: 0.1; Value2: 0.1W; VDC_V: 75; TempCo: 25 ppm/C; SizeArea_mm2: 1.28; SizeX_mm: 1.6; SizeY_mm: 0.8; SizeZ_mm: 1; EIA_Code: E192; U/M: EA; AEC Category: Q200
signal-integrity model Resistor
simulation model Resistor
footprint 0603
footprint 0603M
footprint 0603L
footprint 0603_HV
footprint 0603S
pins: 1, 2

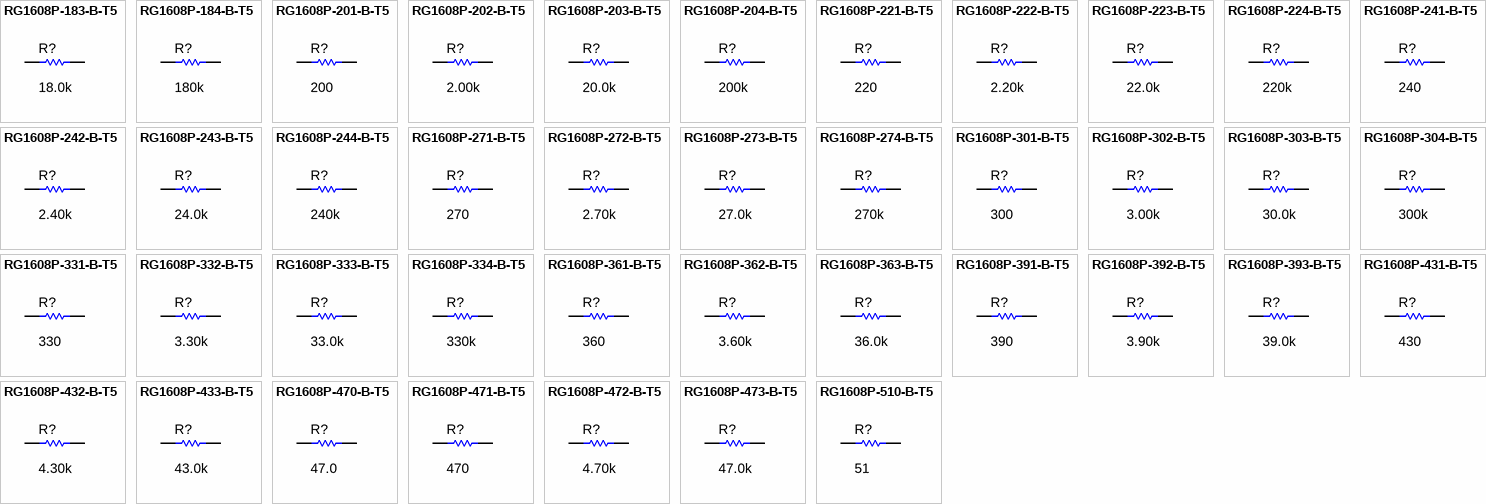
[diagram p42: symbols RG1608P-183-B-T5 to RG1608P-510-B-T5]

## RG1608P-183-B-T5
designator R?  ValueDisplayed: 18.0k  (hidden comment: RG1608P-183-B-T5)
RES, 18.0 k, 0.1%, 0.1 W, 0603; Manufacturer: Susumu Co Ltd; CompType: Resistor; Value: 18.0k; Res_ohm: 18000; Value_Code: 18k0; Tolerance_%: 0.1; Value2: 0.1W; VDC_V: 75; TempCo: 25 ppm/C; SizeArea_mm2: 1.28; SizeX_mm: 1.6; SizeY_mm: 0.8; SizeZ_mm: 1; EIA_Code: E192; U/M: EA; AEC Category: Q200
signal-integrity model Resistor
simulation model Resistor
footprint 0603
footprint 0603M
footprint 0603L
footprint 0603_HV
footprint 0603S
pins: 1, 2

## RG1608P-184-B-T5
designator R?  ValueDisplayed: 180k  (hidden comment: RG1608P-184-B-T5)
RES, 180 k, 0.1%, 0.1 W, 0603; Manufacturer: Susumu Co Ltd; CompType: Resistor; Value: 180k; Res_ohm: 180000; Tolerance_%: 0.1; Value2: 0.1W; VDC_V: 75; TempCo: 25 ppm/C; SizeArea_mm2: 1.28; SizeX_mm: 1.6; SizeY_mm: 0.8; SizeZ_mm: 1; EIA_Code: E192; U/M: EA; AEC Category: Q200; Green_Lifecycle: Active; Green_REACh: Passed
signal-integrity model Resistor
simulation model Resistor
footprint 0603
footprint 0603M
footprint 0603L
footprint 0603_HV
footprint 0603S
pins: 1, 2

## RG1608P-201-B-T5
designator R?  ValueDisplayed: 200  (hidden comment: RG1608P-201-B-T5)
RES, 200, 0.1%, 0.1 W, 0603; Manufacturer: Susumu Co Ltd; CompType: Resistor; Value: 200; Value_Code: 200R; Tolerance_%: 0.1; Value2: 0.1W; VDC_V: 75; TempCo: 25 ppm/C; SizeArea_mm2: 1.28; SizeX_mm: 1.6; SizeY_mm: 0.8; SizeZ_mm: 1; EIA_Code: E192; U/M: EA; AEC Category: Q200; Green_Lifecycle: Active; Green_REACh: Passed
signal-integrity model Resistor
simulation model Resistor
footprint 0603
footprint 0603M
footprint 0603L
footprint 0603_HV
footprint 0603S
pins: 1, 2

## RG1608P-202-B-T5
designator R?  ValueDisplayed: 2.00k  (hidden comment: RG1608P-202-B-T5)
RES, 2.00 k, 0.1%, 0.1 W, 0603; Manufacturer: Susumu Co Ltd; CompType: Resistor; Value: 2.00k; Res_ohm: 2000; Value_Code: 2k00; Tolerance_%: 0.1; Value2: 0.1W; VDC_V: 75; TempCo: 25 ppm/C; SizeArea_mm2: 1.28; SizeX_mm: 1.6; SizeY_mm: 0.8; SizeZ_mm: 1; EIA_Code: E192; U/M: EA; AEC Category: Q200; Green_Lifecycle: Active; Green_REACh: Passed
signal-integrity model Resistor
simulation model Resistor
footprint 0603
footprint 0603M
footprint 0603L
footprint 0603_HV
footprint 0603S
pins: 1, 2

## RG1608P-203-B-T5
designator R?  ValueDisplayed: 20.0k  (hidden comment: RG1608P-203-B-T5)
RES, 20.0 k, 0.1%, 0.1 W, 0603; Manufacturer: Susumu Co Ltd; CompType: Resistor; Value: 20.0k; Res_ohm: 20000; Value_Code: 20k0; Tolerance_%: 0.1; Value2: 0.1W; VDC_V: 75; TempCo: 25 ppm/C; SizeArea_mm2: 1.28; SizeX_mm: 1.6; SizeY_mm: 0.8; SizeZ_mm: 1; EIA_Code: E192; U/M: EA; AEC Category: Q200; Green_Lifecycle: Active; Green_REACh: Passed
signal-integrity model Resistor
simulation model Resistor
footprint 0603
footprint 0603M
footprint 0603L
footprint 0603_HV
footprint 0603S
pins: 1, 2

## RG1608P-204-B-T5
designator R?  ValueDisplayed: 200k  (hidden comment: RG1608P-204-B-T5)
RES, 200 k, 0.1%, 0.1 W, 0603; Manufacturer: Susumu Co Ltd; CompType: Resistor; Value: 200k; Res_ohm: 200000; Tolerance_%: 0.1; Value2: 0.1W; VDC_V: 75; TempCo: 25 ppm/C; SizeArea_mm2: 1.28; SizeX_mm: 1.6; SizeY_mm: 0.8; SizeZ_mm: 1; EIA_Code: E192; U/M: EA; AEC Category: Q200
signal-integrity model Resistor
simulation model Resistor
footprint 0603
footprint 0603M
footprint 0603L
footprint 0603_HV
footprint 0603S
pins: 1, 2

## RG1608P-221-B-T5
designator R?  ValueDisplayed: 220  (hidden comment: RG1608P-221-B-T5)
RES, 220, 0.1%, 0.1 W, 0603; Manufacturer: Susumu Co Ltd; CompType: Resistor; Value: 220; Value_Code: 220R; Tolerance_%: 0.1; Value2: 0.1W; VDC_V: 75; TempCo: 25 ppm/C; SizeArea_mm2: 1.28; SizeX_mm: 1.6; SizeY_mm: 0.8; SizeZ_mm: 1; U/M: EA; AEC Category: Q200
signal-integrity model Resistor
simulation model Resistor
footprint 0603
footprint 0603M
footprint 0603L
footprint 0603_HV
footprint 0603S
pins: 1, 2

## RG1608P-222-B-T5
designator R?  ValueDisplayed: 2.20k  (hidden comment: RG1608P-222-B-T5)
RES, 2.20 k, 0.1%, 0.1 W, 0603; Manufacturer: Susumu Co Ltd; CompType: Resistor; Value: 2.20k; Res_ohm: 2200; Value_Code: 2k20; Tolerance_%: 0.1; Value2: 0.1W; VDC_V: 75; TempCo: 25 ppm/C; SizeArea_mm2: 1.28; SizeX_mm: 1.6; SizeY_mm: 0.8; SizeZ_mm: 1; U/M: EA; AEC Category: Q200; Green_Lifecycle: Active; Green_REACh: Passed
signal-integrity model Resistor
simulation model Resistor
footprint 0603
footprint 0603M
footprint 0603L
footprint 0603_HV
footprint 0603S
pins: 1, 2

## RG1608P-223-B-T5
designator R?  ValueDisplayed: 22.0k  (hidden comment: RG1608P-223-B-T5)
RES, 22.0 k, 0.1%, 0.1 W, 0603; Manufacturer: Susumu Co Ltd; CompType: Resistor; Value: 22.0k; Res_ohm: 22000; Value_Code: 22k0; Tolerance_%: 0.1; Value2: 0.1W; VDC_V: 75; TempCo: 25 ppm/C; SizeArea_mm2: 1.28; SizeX_mm: 1.6; SizeY_mm: 0.8; SizeZ_mm: 1; U/M: EA; AEC Category: Q200
signal-integrity model Resistor
simulation model Resistor
footprint 0603
footprint 0603M
footprint 0603L
footprint 0603_HV
footprint 0603S
pins: 1, 2

## RG1608P-224-B-T5
designator R?  ValueDisplayed: 220k  (hidden comment: RG1608P-224-B-T5)
RES, 220 k, 0.1%, 0.1 W, 0603; Manufacturer: Susumu Co Ltd; CompType: Resistor; Value: 220k; Res_ohm: 220000; Tolerance_%: 0.1; Value2: 0.1W; VDC_V: 75; TempCo: 25 ppm/C; SizeArea_mm2: 1.28; SizeX_mm: 1.6; SizeY_mm: 0.8; SizeZ_mm: 1; U/M: EA; AEC Category: Q200
signal-integrity model Resistor
simulation model Resistor
footprint 0603
footprint 0603M
footprint 0603L
footprint 0603_HV
footprint 0603S
pins: 1, 2

## RG1608P-241-B-T5
designator R?  ValueDisplayed: 240  (hidden comment: RG1608P-241-B-T5)
RES, 240, 0.1%, 0.1 W, 0603; Manufacturer: Susumu Co Ltd; CompType: Resistor; Value: 240; Value_Code: 240R; Tolerance_%: 0.1; Value2: 0.1W; VDC_V: 75; TempCo: 25 ppm/C; SizeArea_mm2: 1.28; SizeX_mm: 1.6; SizeY_mm: 0.8; SizeZ_mm: 1; EIA_Code: E192; U/M: EA; AEC Category: Q200
signal-integrity model Resistor
simulation model Resistor
footprint 0603
footprint 0603M
footprint 0603L
footprint 0603_HV
footprint 0603S
pins: 1, 2

## RG1608P-242-B-T5
designator R?  ValueDisplayed: 2.40k  (hidden comment: RG1608P-242-B-T5)
RES, 2.40 k, 0.1%, 0.1 W, 0603; Manufacturer: Susumu Co Ltd; CompType: Resistor; Value: 2.40k; Res_ohm: 2400; Value_Code: 2k40; Tolerance_%: 0.1; Value2: 0.1W; VDC_V: 75; TempCo: 25 ppm/C; SizeArea_mm2: 1.28; SizeX_mm: 1.6; SizeY_mm: 0.8; SizeZ_mm: 1; EIA_Code: E192; U/M: EA; AEC Category: Q200
signal-integrity model Resistor
simulation model Resistor
footprint 0603
footprint 0603M
footprint 0603L
footprint 0603_HV
footprint 0603S
pins: 1, 2

## RG1608P-243-B-T5
designator R?  ValueDisplayed: 24.0k  (hidden comment: RG1608P-243-B-T5)
RES, 24.0 k, 0.1%, 0.1 W, 0603; Manufacturer: Susumu Co Ltd; CompType: Resistor; Value: 24.0k; Res_ohm: 24000; Value_Code: 24k0; Tolerance_%: 0.1; Value2: 0.1W; VDC_V: 75; TempCo: 25 ppm/C; SizeArea_mm2: 1.28; SizeX_mm: 1.6; SizeY_mm: 0.8; SizeZ_mm: 1; EIA_Code: E192; U/M: EA; AEC Category: Q200; Green_Lifecycle: Active; Green_REACh: Passed
signal-integrity model Resistor
simulation model Resistor
footprint 0603
footprint 0603M
footprint 0603L
footprint 0603_HV
footprint 0603S
pins: 1, 2

## RG1608P-244-B-T5
designator R?  ValueDisplayed: 240k  (hidden comment: RG1608P-244-B-T5)
RES, 240 k, 0.1%, 0.1 W, 0603; Manufacturer: Susumu Co Ltd; CompType: Resistor; Value: 240k; Res_ohm: 240000; Tolerance_%: 0.1; Value2: 0.1W; VDC_V: 75; TempCo: 25 ppm/C; SizeArea_mm2: 1.28; SizeX_mm: 1.6; SizeY_mm: 0.8; SizeZ_mm: 1; EIA_Code: E192; U/M: EA; AEC Category: Q200
signal-integrity model Resistor
simulation model Resistor
footprint 0603
footprint 0603M
footprint 0603L
footprint 0603_HV
footprint 0603S
pins: 1, 2

## RG1608P-271-B-T5
designator R?  ValueDisplayed: 270  (hidden comment: RG1608P-271-B-T5)
RES, 270, 0.1%, 0.1 W, 0603; Manufacturer: Susumu Co Ltd; CompType: Resistor; Value: 270; Value_Code: 270R; Tolerance_%: 0.1; Value2: 0.1W; VDC_V: 75; TempCo: 25 ppm/C; SizeArea_mm2: 1.28; SizeX_mm: 1.6; SizeY_mm: 0.8; SizeZ_mm: 1; U/M: EA; AEC Category: Q200
signal-integrity model Resistor
simulation model Resistor
footprint 0603
footprint 0603M
footprint 0603L
footprint 0603_HV
footprint 0603S
pins: 1, 2

## RG1608P-272-B-T5
designator R?  ValueDisplayed: 2.70k  (hidden comment: RG1608P-272-B-T5)
RES, 2.70 k, 0.1%, 0.1 W, 0603; Manufacturer: Susumu Co Ltd; CompType: Resistor; Value: 2.70k; Res_ohm: 2700; Value_Code: 2k70; Tolerance_%: 0.1; Value2: 0.1W; VDC_V: 75; TempCo: 25 ppm/C; SizeArea_mm2: 1.28; SizeX_mm: 1.6; SizeY_mm: 0.8; SizeZ_mm: 1; U/M: EA; AEC Category: Q200
signal-integrity model Resistor
simulation model Resistor
footprint 0603
footprint 0603M
footprint 0603L
footprint 0603_HV
footprint 0603S
pins: 1, 2

## RG1608P-273-B-T5
designator R?  ValueDisplayed: 27.0k  (hidden comment: RG1608P-273-B-T5)
RES, 27.0 k, 0.1%, 0.1 W, 0603; Manufacturer: Susumu Co Ltd; CompType: Resistor; Value: 27.0k; Res_ohm: 27000; Value_Code: 27k0; Tolerance_%: 0.1; Value2: 0.1W; VDC_V: 75; TempCo: 25 ppm/C; SizeArea_mm2: 1.28; SizeX_mm: 1.6; SizeY_mm: 0.8; SizeZ_mm: 1; U/M: EA; AEC Category: Q200
signal-integrity model Resistor
simulation model Resistor
footprint 0603
footprint 0603M
footprint 0603L
footprint 0603_HV
footprint 0603S
pins: 1, 2

## RG1608P-274-B-T5
designator R?  ValueDisplayed: 270k  (hidden comment: RG1608P-274-B-T5)
RES, 270 k, 0.1%, 0.1 W, 0603; Manufacturer: Susumu Co Ltd; CompType: Resistor; Value: 270k; Res_ohm: 270000; Tolerance_%: 0.1; Value2: 0.1W; VDC_V: 75; TempCo: 25 ppm/C; SizeArea_mm2: 1.28; SizeX_mm: 1.6; SizeY_mm: 0.8; SizeZ_mm: 1; U/M: EA; AEC Category: Q200
signal-integrity model Resistor
simulation model Resistor
footprint 0603
footprint 0603M
footprint 0603L
footprint 0603_HV
footprint 0603S
pins: 1, 2

## RG1608P-301-B-T5
designator R?  ValueDisplayed: 300  (hidden comment: RG1608P-301-B-T5)
RES, 300, 0.1%, 0.1 W, 0603; Manufacturer: Susumu Co Ltd; CompType: Resistor; Value: 300; Value_Code: 300R; Tolerance_%: 0.1; Value2: 0.1W; VDC_V: 75; TempCo: 25 ppm/C; SizeArea_mm2: 1.28; SizeX_mm: 1.6; SizeY_mm: 0.8; SizeZ_mm: 1; U/M: EA; AEC Category: Q200
signal-integrity model Resistor
simulation model Resistor
footprint 0603
footprint 0603M
footprint 0603L
footprint 0603_HV
footprint 0603S
pins: 1, 2

## RG1608P-302-B-T5
designator R?  ValueDisplayed: 3.00k  (hidden comment: RG1608P-302-B-T5)
RES, 3.00 k, 0.1%, 0.1 W, 0603; Manufacturer: Susumu Co Ltd; CompType: Resistor; Value: 3.00k; Res_ohm: 3000; Value_Code: 3k00; Tolerance_%: 0.1; Value2: 0.1W; VDC_V: 75; TempCo: 25 ppm/C; SizeArea_mm2: 1.28; SizeX_mm: 1.6; SizeY_mm: 0.8; SizeZ_mm: 1; U/M: EA; AEC Category: Q200
signal-integrity model Resistor
simulation model Resistor
footprint 0603
footprint 0603M
footprint 0603L
footprint 0603_HV
footprint 0603S
pins: 1, 2

## RG1608P-303-B-T5
designator R?  ValueDisplayed: 30.0k  (hidden comment: RG1608P-303-B-T5)
RES, 30.0 k, 0.1%, 0.1 W, 0603; Manufacturer: Susumu Co Ltd; CompType: Resistor; Value: 30.0k; Res_ohm: 30000; Value_Code: 30k0; Tolerance_%: 0.1; Value2: 0.1W; VDC_V: 75; TempCo: 25 ppm/C; SizeArea_mm2: 1.28; SizeX_mm: 1.6; SizeY_mm: 0.8; SizeZ_mm: 1; U/M: EA; AEC Category: Q200; Green_Lifecycle: Active; Green_REACh: Passed
signal-integrity model Resistor
simulation model Resistor
footprint 0603
footprint 0603M
footprint 0603L
footprint 0603_HV
footprint 0603S
pins: 1, 2

## RG1608P-304-B-T5
designator R?  ValueDisplayed: 300k  (hidden comment: RG1608P-304-B-T5)
RES, 300 k, 0.1%, 0.1 W, 0603; Manufacturer: Susumu Co Ltd; CompType: Resistor; Value: 300k; Res_ohm: 300000; Tolerance_%: 0.1; Value2: 0.1W; VDC_V: 75; TempCo: 25 ppm/C; SizeArea_mm2: 1.28; SizeX_mm: 1.6; SizeY_mm: 0.8; SizeZ_mm: 1; U/M: EA; AEC Category: Q200; Green_Lifecycle: Active; Green_REACh: Passed
signal-integrity model Resistor
simulation model Resistor
footprint 0603
footprint 0603M
footprint 0603L
footprint 0603_HV
footprint 0603S
pins: 1, 2

## RG1608P-331-B-T5
designator R?  ValueDisplayed: 330  (hidden comment: RG1608P-331-B-T5)
RES, 330, 0.1%, 0.1 W, 0603; Manufacturer: Susumu Co Ltd; CompType: Resistor; Value: 330; Value_Code: 330R; Tolerance_%: 0.1; Value2: 0.1W; VDC_V: 75; TempCo: 25 ppm/C; SizeArea_mm2: 1.28; SizeX_mm: 1.6; SizeY_mm: 0.8; SizeZ_mm: 1; U/M: EA; AEC Category: Q200
signal-integrity model Resistor
simulation model Resistor
footprint 0603
footprint 0603M
footprint 0603L
footprint 0603_HV
footprint 0603S
pins: 1, 2

## RG1608P-332-B-T5
designator R?  ValueDisplayed: 3.30k  (hidden comment: RG1608P-332-B-T5)
RES, 3.30 k, 0.1%, 0.1 W, 0603; Manufacturer: Susumu Co Ltd; CompType: Resistor; Value: 3.30k; Res_ohm: 3300; Value_Code: 3k30; Tolerance_%: 0.1; Value2: 0.1W; VDC_V: 75; TempCo: 25 ppm/C; SizeArea_mm2: 1.28; SizeX_mm: 1.6; SizeY_mm: 0.8; SizeZ_mm: 1; U/M: EA; AEC Category: Q200; Green_Lifecycle: Active; Green_REACh: Passed
signal-integrity model Resistor
simulation model Resistor
footprint 0603
footprint 0603M
footprint 0603L
footprint 0603_HV
footprint 0603S
pins: 1, 2

## RG1608P-333-B-T5
designator R?  ValueDisplayed: 33.0k  (hidden comment: RG1608P-333-B-T5)
RES, 33.0 k, 0.1%, 0.1 W, 0603; Manufacturer: Susumu Co Ltd; CompType: Resistor; Value: 33.0k; Res_ohm: 33000; Value_Code: 33k0; Tolerance_%: 0.1; Value2: 0.1W; VDC_V: 75; TempCo: 25 ppm/C; SizeArea_mm2: 1.28; SizeX_mm: 1.6; SizeY_mm: 0.8; SizeZ_mm: 1; U/M: EA; AEC Category: Q200
signal-integrity model Resistor
simulation model Resistor
footprint 0603
footprint 0603M
footprint 0603L
footprint 0603_HV
footprint 0603S
pins: 1, 2

## RG1608P-334-B-T5
designator R?  ValueDisplayed: 330k  (hidden comment: RG1608P-334-B-T5)
RES, 330 k, 0.1%, 0.1 W, 0603; Manufacturer: Susumu Co Ltd; CompType: Resistor; Value: 330k; Res_ohm: 330000; Tolerance_%: 0.1; Value2: 0.1W; VDC_V: 75; TempCo: 25 ppm/C; SizeArea_mm2: 1.28; SizeX_mm: 1.6; SizeY_mm: 0.8; SizeZ_mm: 1; U/M: EA; AEC Category: Q200; Green_Lifecycle: Active; Green_REACh: Passed
signal-integrity model Resistor
simulation model Resistor
footprint 0603
footprint 0603M
footprint 0603L
footprint 0603_HV
footprint 0603S
pins: 1, 2

## RG1608P-361-B-T5
designator R?  ValueDisplayed: 360  (hidden comment: RG1608P-361-B-T5)
RES, 360, 0.1%, 0.1 W, 0603; Manufacturer: Susumu Co Ltd; CompType: Resistor; Value: 360; Value_Code: 360R; Tolerance_%: 0.1; Value2: 0.1W; VDC_V: 75; TempCo: 25 ppm/C; SizeArea_mm2: 1.28; SizeX_mm: 1.6; SizeY_mm: 0.8; SizeZ_mm: 1; U/M: EA; AEC Category: Q200
signal-integrity model Resistor
simulation model Resistor
footprint 0603
footprint 0603M
footprint 0603L
footprint 0603_HV
footprint 0603S
pins: 1, 2

## RG1608P-362-B-T5
designator R?  ValueDisplayed: 3.60k  (hidden comment: RG1608P-362-B-T5)
RES, 3.60 k, 0.1%, 0.1 W, 0603; Manufacturer: Susumu Co Ltd; CompType: Resistor; Value: 3.60k; Res_ohm: 3600; Value_Code: 3k60; Tolerance_%: 0.1; Value2: 0.1W; VDC_V: 75; TempCo: 25 ppm/C; SizeArea_mm2: 1.28; SizeX_mm: 1.6; SizeY_mm: 0.8; SizeZ_mm: 1; U/M: EA; AEC Category: Q200
signal-integrity model Resistor
simulation model Resistor
footprint 0603
footprint 0603M
footprint 0603L
footprint 0603_HV
footprint 0603S
pins: 1, 2

## RG1608P-363-B-T5
designator R?  ValueDisplayed: 36.0k  (hidden comment: RG1608P-363-B-T5)
RES, 36.0 k, 0.1%, 0.1 W, 0603; Manufacturer: Susumu Co Ltd; CompType: Resistor; Value: 36.0k; Res_ohm: 36000; Value_Code: 36k0; Tolerance_%: 0.1; Value2: 0.1W; VDC_V: 75; TempCo: 25 ppm/C; SizeArea_mm2: 1.28; SizeX_mm: 1.6; SizeY_mm: 0.8; SizeZ_mm: 1; U/M: EA; AEC Category: Q200
signal-integrity model Resistor
simulation model Resistor
footprint 0603
footprint 0603M
footprint 0603L
footprint 0603_HV
footprint 0603S
pins: 1, 2

## RG1608P-391-B-T5
designator R?  ValueDisplayed: 390  (hidden comment: RG1608P-391-B-T5)
RES, 390, 0.1%, 0.1 W, 0603; Manufacturer: Susumu Co Ltd; CompType: Resistor; Value: 390; Value_Code: 390R; Tolerance_%: 0.1; Value2: 0.1W; VDC_V: 75; TempCo: 25 ppm/C; SizeArea_mm2: 1.28; SizeX_mm: 1.6; SizeY_mm: 0.8; SizeZ_mm: 1; U/M: EA; AEC Category: Q200
signal-integrity model Resistor
simulation model Resistor
footprint 0603
footprint 0603M
footprint 0603L
footprint 0603_HV
footprint 0603S
pins: 1, 2

## RG1608P-392-B-T5
designator R?  ValueDisplayed: 3.90k  (hidden comment: RG1608P-392-B-T5)
RES, 3.90 k, 0.1%, 0.1 W, 0603; Manufacturer: Susumu Co Ltd; CompType: Resistor; Value: 3.90k; Res_ohm: 3900; Value_Code: 3k90; Tolerance_%: 0.1; Value2: 0.1W; VDC_V: 75; TempCo: 25 ppm/C; SizeArea_mm2: 1.28; SizeX_mm: 1.6; SizeY_mm: 0.8; SizeZ_mm: 1; U/M: EA; AEC Category: Q200
signal-integrity model Resistor
simulation model Resistor
footprint 0603
footprint 0603M
footprint 0603L
footprint 0603_HV
footprint 0603S
pins: 1, 2

## RG1608P-393-B-T5
designator R?  ValueDisplayed: 39.0k  (hidden comment: RG1608P-393-B-T5)
RES, 39.0 k, 0.1%, 0.1 W, 0603; Manufacturer: Susumu Co Ltd; CompType: Resistor; Value: 39.0k; Res_ohm: 39000; Value_Code: 39k0; Tolerance_%: 0.1; Value2: 0.1W; VDC_V: 75; TempCo: 25 ppm/C; SizeArea_mm2: 1.28; SizeX_mm: 1.6; SizeY_mm: 0.8; SizeZ_mm: 1; U/M: EA; AEC Category: Q200
signal-integrity model Resistor
simulation model Resistor
footprint 0603
footprint 0603M
footprint 0603L
footprint 0603_HV
footprint 0603S
pins: 1, 2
